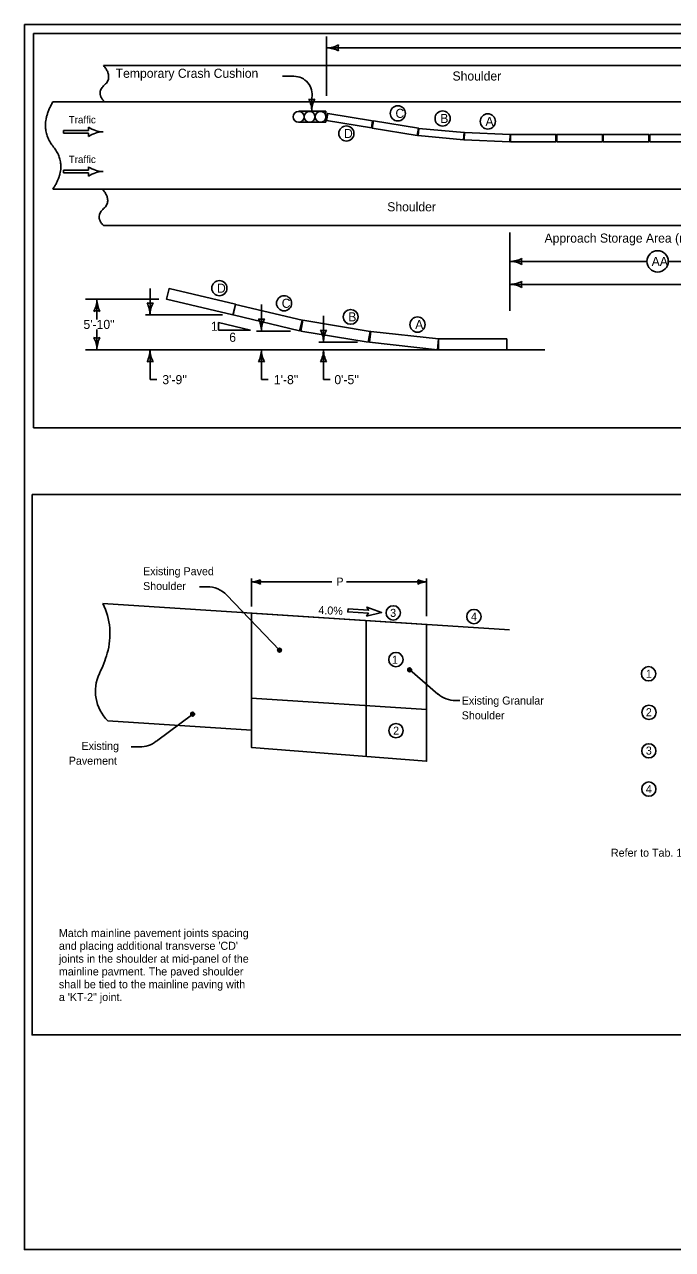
# Model space of a CAD drawing. Extents: x 8045 to 81668, y 6217 to 16762.
# Drawn here: x 13733 to 14801, y 7924 to 9944 of the extents above; entities that cross this region are included whole.
import ezdxf

# ---------------------------------------------------------------- set-up
doc = ezdxf.new("R2010")
doc.units = 0
for name, color, linetype in [('dsnNonPlotable', 7, 'Continuous'), ('dsnStdBlock', 7, 'Continuous'), ('dsnStdBlockModified', 7, 'Continuous'), ('dsnStdBorder', 7, 'Continuous'), ('dsnStdLineWork', 7, 'Continuous'), ('dsnStdNameDate', 7, 'Continuous'), ('dsnStdSection', 7, 'Continuous'), ('Level 5', 7, 'Continuous')]:
    doc.layers.add(name, color=color, linetype=linetype)

msp = doc.modelspace()

# ---------------------------------------------------------------- linework, layer by layer
at = {"layer": 'dsnNonPlotable'}
for p, q in [((14230.5, 9924.1), (14230.5, 9826.6)), ((14230.5, 9905.4), (15109, 9905.4)), ((13862.8, 9876.4), (14991.3, 9876.4)), ((14176.7, 9858.7), (14158, 9858.7)), ((14206.2, 9823.4), (14206.2, 9800.9)), ((13779.2, 9816.4), (15021.3, 9816.4)), ((14184.6, 9800.9), (14229.6, 9800.9)), ((14229.6, 9800.9), (14229.6, 9782.8)), ((14229.6, 9782.8), (14184.6, 9782.8)), ((14228.4, 9788.6), (14229.7, 9788.3)), ((14230.1, 9784.9), (14230.1, 9784.9)), ((13838.1, 9769.3), (13796.8, 9769.3)), ((13796.8, 9769.3), (13796.8, 9764.8)), ((13796.8, 9764.8), (13838.1, 9764.8)), ((13838.1, 9774.5), (13838.1, 9769.3)), ((13838.1, 9764.8), (13838.1, 9759.5)), ((13862, 9767), (13862, 9767)), ((13838.1, 9703.8), (13796.8, 9703.8)), ((13796.8, 9703.8), (13796.8, 9699.3)), ((13796.8, 9699.3), (13838.1, 9699.3)), ((13838.1, 9709.1), (13838.1, 9703.8)), ((13838.1, 9699.3), (13838.1, 9694.1)), ((13862, 9701.6), (13862, 9701.6)), ((13779.2, 9672.4), (15021.3, 9672.4)), ((13862.8, 9612.4), (14991.3, 9612.4)), ((14532.6, 9601.2), (14532.6, 9472)), ((14532.6, 9553.4), (14758.7, 9553.4)), ((14794, 9553.4), (15020.1, 9553.4)), ((14532.6, 9515.5), (15123.4, 9515.5)), ((13939.5, 9508.5), (13939.5, 9465)), ((13954.1, 9491), (13832.9, 9491)), ((13851.9, 9491), (13851.9, 9457.5)), ((14123.1, 9482.1), (14123.1, 9438.6)), ((14059, 9465), (13931.8, 9465)), ((14225.5, 9463.5), (14225.5, 9420.1)), ((13851.9, 9441.2), (13851.9, 9407.7)), ((14170.9, 9438.6), (14115.3, 9438.6)), ((14281.8, 9420.1), (14217.7, 9420.1)), ((14590.3, 9407.7), (13832.9, 9407.7)), ((13939.5, 9407.7), (13939.5, 9358.5)), ((14123.1, 9407.7), (14123.1, 9358.5)), ((14225.5, 9407.7), (14225.5, 9380.8)), ((14225.5, 9380.8), (14225.5, 9358.5)), ((13939.5, 9358.5), (13950.7, 9358.5)), ((14123.1, 9358.5), (14134.3, 9358.5)), ((14225.5, 9358.5), (14236.6, 9358.5))]:
    msp.add_line(p, q, dxfattribs=at)
for points in [[(14306.4, 9785.3), (14232.4, 9797.4), (14230.5, 9785.6), (14304.5, 9773.4)], [(14381.9, 9772.9), (14307.9, 9785), (14306, 9773.2), (14380, 9761)], [(14457.3, 9765.7), (14382.7, 9772.8), (14381.5, 9760.8), (14456.2, 9753.7)], [(14533.1, 9762.7), (14458.2, 9765.7), (14457.7, 9753.7), (14532.6, 9750.7)], [(14533.8, 9762.7), (14608.8, 9762.7), (14608.8, 9750.7), (14533.8, 9750.7)], [(14610.3, 9762.7), (14685.3, 9762.7), (14685.3, 9750.7), (14610.3, 9750.7)], [(14686.8, 9762.7), (14761.8, 9762.7), (14761.8, 9750.7), (14686.8, 9750.7)], [(14763.3, 9762.7), (14838.3, 9762.7), (14838.3, 9750.7), (14763.3, 9750.7)], [(14080.3, 9482.6), (13970.9, 9508.5), (13966.7, 9491), (14076.2, 9465.1)], [(14190.1, 9456.6), (14080.6, 9482.5), (14076.5, 9465), (14186, 9439.1)], [(14302.2, 9437.9), (14191.2, 9456.4), (14188.3, 9438.6), (14299.2, 9420.2)], [(14415.3, 9425.6), (14303.5, 9437.9), (14301.5, 9420.1), (14413.3, 9407.7)], [(14527.8, 9425.7), (14415.3, 9425.7), (14415.3, 9407.7), (14527.8, 9407.7)]]:
    msp.add_lwpolyline(points, close=True, dxfattribs=at)
for centre, radius in [((14184.6, 9791.8), 9), ((14184.6, 9791.8), 9), ((14202.6, 9791.8), 9), ((14202.6, 9791.8), 9), ((14220.6, 9791.8), 9), ((14220.6, 9791.8), 9), ((14348.1, 9797.5), 12.5), ((14421.9, 9789.1), 12.5), ((14263.2, 9764.3), 12.5), ((14496.4, 9784.2), 12.5), ((14776.4, 9553.4), 17.6), ((14053.8, 9509.2), 12.5), ((14160.5, 9484.3), 12.5), ((14270.2, 9461.9), 12.2), ((14380.5, 9449.2), 12.5)]:
    msp.add_circle(centre, radius, dxfattribs=at)
for centre, radius, start, end in [((14230.5, 9947.9), 42.5, 270, 298.0725), ((14230.5, 9862.9), 42.5, 61.9275, 90), ((14266.1, 9905.4), 16.4, 162.2666, 197.7334), ((14176.7, 9828.7), 30, 349.6463, 90), ((14206.2, 9836.5), 16.4, 252.2666, 287.7333), ((14163.7, 9800.9), 42.5, 360, 28.0725), ((14248.7, 9800.9), 42.5, 151.9275, 180), ((13864, 9815.4), 48.4, 237.618, 267.648), ((13864, 9718.7), 48.4, 92.352, 122.382), ((13864, 9749.9), 48.4, 237.618, 267.648), ((13864, 9653.3), 48.4, 92.352, 122.382), ((14532.6, 9595.9), 42.5, 270, 298.0725), ((14568.3, 9553.4), 16.4, 162.2666, 197.7334), ((14532.6, 9510.9), 42.5, 61.9275, 90), ((14532.6, 9558), 42.5, 270, 298.0725), ((14532.6, 9473), 42.5, 61.9275, 90), ((14568.3, 9515.5), 16.4, 162.2666, 197.7334), ((13809.4, 9491), 42.5, 331.9275, 0), ((13894.4, 9491), 42.5, 180, 208.0725), ((13939.5, 9500.7), 16.4, 252.2666, 287.7334), ((13897, 9465), 42.5, 0, 28.0725), ((13982, 9465), 42.5, 151.9275, 180), ((13851.9, 9455.4), 16.4, 72.2666, 107.7334), ((14123.1, 9474.3), 16.4, 252.2666, 287.7334), ((14080.6, 9438.6), 42.5, 0, 28.0725), ((14165.6, 9438.6), 42.5, 151.9275, 180), ((14225.5, 9455.7), 16.4, 252.2666, 287.7334), ((14183, 9420.1), 42.5, 0, 28.0725), ((14268, 9420.1), 42.5, 151.9275, 180), ((13851.9, 9443.4), 16.4, 252.2666, 287.7334), ((13809.4, 9407.7), 42.5, 0, 28.0725), ((13894.4, 9407.7), 42.5, 151.9275, 180), ((13897, 9407.7), 42.5, 331.9275, 0), ((13982, 9407.7), 42.5, 180, 208.0725), ((14080.6, 9407.7), 42.5, 331.9275, 0), ((14165.6, 9407.7), 42.5, 180, 208.0725), ((14183, 9407.7), 42.5, 331.9275, 0), ((14268, 9407.7), 42.5, 180, 208.0725), ((13939.5, 9372.1), 16.4, 72.2666, 107.7334), ((14123.1, 9372.1), 16.4, 72.2666, 107.7334), ((14225.5, 9372.1), 16.4, 72.2666, 107.7334)]:
    msp.add_arc(centre, radius, start, end, dxfattribs=at)
for points in [[(13862.8, 9876.4), (13878.9, 9857.1), (13850, 9831.5), (13864.4, 9816.5)], [(13779.2, 9816.4), (13754.6, 9773.8), (13805.3, 9711.6), (13779.2, 9672.4)], [(13861.2, 9672.4), (13877.3, 9653.1), (13848.4, 9627.5), (13862.8, 9612.4)]]:
    msp.add_open_spline(points, degree=2, dxfattribs=at)
at = {"layer": 'dsnStdBlock'}
msp.add_line((13747.5, 9929), (13747.5, 9929), dxfattribs=at)
at = {"layer": 'dsnStdBlockModified'}
for p, q in [((13747.5, 9929), (16852.5, 9929)), ((13747.5, 9279), (13747.5, 9929))]:
    msp.add_line(p, q, dxfattribs=at)
at = {"layer": 'dsnStdBorder'}
msp.add_line((16852.5, 9279), (13747.5, 9279), dxfattribs=at)
at = {"layer": 'dsnStdLineWork'}
for p, q in [((14107, 8984.2), (14107, 9030.4)), ((14395.5, 8968.1), (14395.5, 9030.4)), ((14020.9, 9017), (14033.6, 9017)), ((14107, 9024.9), (14239.3, 9024.9)), ((14107.1, 9024.9), (14120.9, 9024.9)), ((14263.2, 9024.9), (14395.5, 9024.9)), ((14395.5, 9024.9), (14381.7, 9024.9)), ((13861.7, 8989.1), (14532, 8945.8)), ((14066.1, 9003.2), (14153.2, 8912.4)), ((14295.8, 8736.8), (14295.8, 8961)), ((14414.1, 8840), (14367.8, 8879.7)), ((14107, 8832.9), (14395.5, 8814.2)), ((14450.3, 8829.2), (14443.4, 8829.2)), ((13869.8, 8795.8), (14107, 8780.5)), ((13949.9, 8762), (14009.9, 8807)), ((13922.4, 8752.7), (13908.4, 8752.7))]:
    msp.add_line(p, q, dxfattribs=at)
for points in [[(14120.6, 9022.3), (14120.1, 9024.9), (14120.6, 9027.5), (14117.5, 9026), (14112.6, 9024.9), (14117.9, 9023.6), (14120.2, 9022.6), (14119.6, 9024.9), (14119.8, 9026.5), (14117.8, 9025.6), (14115.1, 9024.9), (14118, 9024), (14119.5, 9023.5), (14119.2, 9025.7), (14117.2, 9024.9), (14118.8, 9024.4), (14118.8, 9025.1), (14118.1, 9024.9)], [(14382, 9027.4), (14382.5, 9024.8), (14382, 9022.2), (14385.1, 9023.7), (14390, 9024.8), (14384.7, 9026.1), (14382.4, 9027.1), (14383, 9024.8), (14382.8, 9023.2), (14384.8, 9024.1), (14387.5, 9024.8), (14384.6, 9025.7), (14383.1, 9026.2), (14383.4, 9024), (14385.4, 9024.8), (14383.8, 9025.3), (14383.8, 9024.6), (14384.5, 9024.8)], [(14107, 8973.5), (14107, 8751.6), (14395.5, 8729), (14395.5, 8954.6)], [(14155.2, 8914.1), (14154.2, 8914.5), (14152.6, 8915.3), (14151.2, 8914.3), (14150.3, 8913.1), (14150.1, 8911.4), (14151.3, 8910.4), (14152.7, 8909.4), (14154.2, 8909.8), (14155.3, 8910.7), (14155.8, 8912.6), (14155.1, 8913.6), (14153.6, 8914.5), (14151.9, 8914.7), (14150.8, 8913.5), (14150.7, 8911.9), (14151.6, 8910.7), (14153, 8909.8), (14153.9, 8910.3), (14154.9, 8910.8), (14155.3, 8912.4), (14154.5, 8913.2), (14153.3, 8914), (14152.1, 8914.2), (14151.5, 8912.8), (14151.6, 8911.5), (14152.6, 8910.5), (14153.3, 8910.8), (14154.3, 8911.1), (14154.5, 8912.3), (14154, 8913.2), (14153, 8913.5), (14152.2, 8912.9), (14152.1, 8912), (14152.6, 8911.2), (14153.1, 8911.1), (14153.7, 8911.3), (14154, 8912.3), (14153.6, 8912.8), (14152.9, 8913), (14152.6, 8912.5), (14152.7, 8912), (14153.1, 8911.5), (14153.4, 8911.8), (14153.2, 8912.4)], [(14369.7, 8881.7), (14368.6, 8882.1), (14367.1, 8882.9), (14365.7, 8881.9), (14364.8, 8880.7), (14364.6, 8879), (14365.8, 8878), (14367.1, 8877), (14368.6, 8877.4), (14369.7, 8878.3), (14370.3, 8880.2), (14369.6, 8881.2), (14368.1, 8882.1), (14366.4, 8882.3), (14365.3, 8881.1), (14365.2, 8879.5), (14366.1, 8878.4), (14367.5, 8877.4), (14368.3, 8877.9), (14369.4, 8878.4), (14369.8, 8880), (14368.9, 8880.8), (14367.8, 8881.6), (14366.5, 8881.8), (14365.9, 8880.4), (14366.1, 8879.1), (14367, 8878.1), (14367.8, 8878.4), (14368.7, 8878.7), (14369, 8879.9), (14368.5, 8880.8), (14367.5, 8881.1), (14366.7, 8880.5), (14366.5, 8879.6), (14367, 8878.8), (14367.6, 8878.7), (14368.2, 8878.9), (14368.4, 8879.9), (14368.1, 8880.4), (14367.3, 8880.6), (14367, 8880.1), (14367.1, 8879.6), (14367.6, 8879.1), (14367.9, 8879.5), (14367.7, 8880)], [(14011.9, 8808.7), (14010.8, 8809.1), (14009.3, 8809.9), (14007.9, 8808.9), (14007, 8807.7), (14006.8, 8806), (14008, 8805), (14009.3, 8804), (14010.8, 8804.3), (14011.9, 8805.2), (14012.5, 8807.2), (14011.8, 8808.2), (14010.3, 8809), (14008.6, 8809.3), (14007.5, 8808.1), (14007.4, 8806.5), (14008.3, 8805.3), (14009.7, 8804.4), (14010.6, 8804.9), (14011.6, 8805.4), (14012, 8806.9), (14011.1, 8807.8), (14010, 8808.6), (14008.7, 8808.7), (14008.1, 8807.4), (14008.3, 8806.1), (14009.2, 8805.1), (14010, 8805.4), (14010.9, 8805.7), (14011.2, 8806.9), (14010.7, 8807.8), (14009.7, 8808.1), (14008.9, 8807.4), (14008.7, 8806.6), (14009.2, 8805.7), (14009.8, 8805.7), (14010.4, 8805.9), (14010.6, 8806.8), (14010.3, 8807.4), (14009.6, 8807.6), (14009.2, 8807.1), (14009.3, 8806.5), (14009.8, 8806.1), (14010.1, 8806.4), (14009.9, 8807)]]:
    msp.add_lwpolyline(points, dxfattribs=at)
for points in [[(14107, 8973.5), (14395.5, 8954.6), (14395.5, 8814.2), (14107, 8832.9)], [(14296.3, 8968.2), (14321.3, 8974.4), (14297.2, 8983.4), (14299.8, 8978.2), (14266, 8980.4), (14265.6, 8975.3), (14299.5, 8973.1)]]:
    msp.add_lwpolyline(points, close=True, dxfattribs=at)
for centre, radius in [((14340.5, 8973.8), 11.8), ((14473.5, 8967.7), 11.8), ((14153, 8912.2), 3.15), ((14344.9, 8896.8), 11.8), ((14367.5, 8879.8), 3.15), ((14761.5, 8873.4), 11.8), ((14009.7, 8806.8), 3.15), ((14762.1, 8809.7), 11.8), ((14345, 8779.6), 11.8), ((14761.9, 8746.3), 11.8), ((14761.9, 8683.2), 11.8)]:
    msp.add_circle(centre, radius, dxfattribs=at)
for centre, radius, start, end in [((14033.6, 8972), 45, 43.8398, 90), ((14107.1, 9055.5), 30.6, 270, 298.0725), ((14107.1, 8994.3), 30.6, 61.9275, 90), ((14132.7, 9024.9), 11.8, 162.2666, 197.7334), ((14369.9, 9024.9), 11.8, 342.2666, 17.7334), ((14395.5, 9055.5), 30.6, 241.9275, 270), ((14395.5, 8994.3), 30.6, 90, 118.0725), ((13760.4, 8939), 113, 343.6708, 26.3373), ((13656.4, 8969.5), 221.4, 334.4332, 343.6708), ((13917.6, 8844.5), 68.2, 154.4332, 225.5564), ((14443.4, 8874.2), 45, 229.3882, 270), ((13922.4, 8797.7), 45, 270, 307.6187)]:
    msp.add_arc(centre, radius, start, end, dxfattribs=at)
at = {"layer": 'dsnStdNameDate'}
msp.add_lwpolyline([(13745, 9169.2), (15295.8, 9169.2), (15295.8, 8277.8), (13745, 8277.8)], close=True, dxfattribs=at)
at = {"layer": 'dsnStdSection'}
msp.add_lwpolyline([(13732.5, 9944), (16867.5, 9944), (16867.5, 7924), (13732.5, 7924)], close=True, dxfattribs=at)
at = {"layer": 'Level 5'}
for p, q in [((14105.1, 9440.1), (14052.5, 9452.5)), ((14052.5, 9452.5), (14052.5, 9440.1)), ((14052.5, 9440.1), (14105.1, 9440.1))]:
    msp.add_line(p, q, dxfattribs=at)

# ---------------------------------------------------------------- texts
at = {"layer": 'dsnStdLineWork'}
for s, p in [('Existing Paved', (13928, 9035.9)), ('P', (14246.7, 9018.8)), ('Shoulder', (13928, 9011.5)), ('3', (14335.4, 8967.2)), ('4', (14468.7, 8961.1)), ('1', (14338.4, 8889.9)), ('1', (14757, 8866.8)), ('Existing Granular', (14453.4, 8822.6)), ('Shoulder', (14453.4, 8798.2)), ('2', (14757, 8803.4)), ('2', (14340.3, 8773)), ('Existing', (13826.5, 8747.8)), ('3', (14757, 8740.1)), ('Pavement', (13805.5, 8723.4)), ('4', (14757, 8676.7)), ('Refer to Tab. 112-9 for P width and Shoulder quantities', (14699.4, 8571.7)), ('Match mainline pavement joints spacing ', (13789.1, 8439.3)), ("and placing additional transverse 'CD' ", (13789.2, 8418.2)), ('joints in the shoulder at mid-panel of the ', (13789.2, 8397)), ('mainline pavment. The paved shoulder ', (13789.2, 8375.9)), ('shall be tied to the mainline paving with ', (13789.2, 8354.8)), ('a \'KT-2" joint.', (13789.2, 8333.7))]:
    msp.add_text(s, height=13.2, dxfattribs=at).set_placement(p)
msp.add_text('4.0%', height=13.2, rotation=357.4961, dxfattribs=at).set_placement((14216.8, 8972))
at = {"layer": 'Level 5'}
for s, height, p in [('Temporary Crash Cushion', 15, (13882.8, 9856.1)), ('Shoulder', 15, (14438.2, 9851.6)), ('C', 15, (14344.2, 9790)), ('Traffic', 12, (13805.5, 9781)), ('B', 15, (14418, 9781.6)), ('A', 15, (14492.5, 9776.7)), ('D', 15, (14259.3, 9756.8)), ('Traffic', 12, (13805.5, 9715.6)), ('Shoulder', 15, (14330.6, 9635.9)), ("Approach Storage Area (minimum 20')", 15, (14589.9, 9584.3)), ('AA', 15, (14766.6, 9545.9)), ('D', 15, (14049.9, 9501.7)), ('C', 15, (14156.6, 9476.8)), ("5'-10''", 15, (13829.7, 9442)), ('1', 15, (14039.9, 9438.9)), ('B', 15, (14266.3, 9454.4)), ('A', 15, (14376.6, 9441.7)), ('6', 15, (14070.1, 9420.8)), ("3'-9''", 15, (13959.8, 9350.9)), ("1'-8''", 15, (14143.7, 9350.9)), ("0'-5''", 15, (14243.4, 9350.9))]:
    msp.add_text(s, height=height, dxfattribs=at).set_placement(p)

doc.saveas('drawing.dxf')
